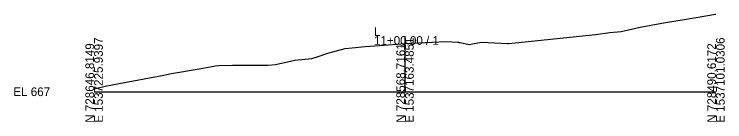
# Model space of a CAD drawing. Extents: x -26 to 1203, y -10 to 9522.
# Drawn here: x -25.7 to 202.8, y 990.3 to 1025 of the extents above; entities that cross this region are included whole.
import ezdxf

# ---------------------------------------------------------------- set-up
doc = ezdxf.new("R2010")
doc.units = 0
for name, color, linetype in [('Default', 7, 'Continuous'), ('Exist Cross Section Cell', 7, 'Continuous'), ('Exist XS Center Line Elevation Label', 7, 'Continuous'), ('Exist XS Ground Line', 7, 'Continuous')]:
    doc.layers.add(name, color=color, linetype=linetype)

msp = doc.modelspace()

# ---------------------------------------------------------------- linework, layer by layer
at = {"layer": 'Exist Cross Section Cell'}
for p, q in [((100, 1000), (100, 1017.92)), ((0, 1000), (100, 1000)), ((100, 1000), (200, 1000))]:
    msp.add_line(p, q, dxfattribs=at)
at = {"layer": 'Exist XS Ground Line'}
msp.add_lwpolyline([(0, 1000.97), (3.54, 1001.77), (8.05, 1002.6), (22.39, 1005.38), (24.94, 1005.89), (34.48, 1007.45), (39.04, 1008.29), (40.12, 1008.45), (44.52, 1008.6), (55.86, 1008.55), (58.33, 1008.8), (64.53, 1010.12), (70.06, 1010.74), (71.74, 1011.29), (75.2, 1012.4), (80.73, 1013.91), (83.04, 1014.18), (87.19, 1014.6), (91.77, 1014.92), (100, 1015.49), (100.13, 1015.5), (108.76, 1015.99), (113.12, 1016.22), (116.94, 1015.96), (117.18, 1015.94), (117.35, 1015.9), (117.66, 1015.85), (120.69, 1015.21), (121.72, 1015.45), (124.55, 1016), (132.97, 1015.51), (133.31, 1015.52), (135.56, 1015.75), (161.21, 1018.45), (165.85, 1019.03), (169.48, 1019.45), (175.59, 1020.8), (182.54, 1022.05), (193.65, 1023.87), (199.84, 1024.96), (200, 1024.98)], dxfattribs=at)

# ---------------------------------------------------------------- texts
at = {"layer": 'Default'}
msp.add_text('-', height=0.0001, dxfattribs=at).set_placement((0, 1000))
msp.add_text('-', height=0.0001, dxfattribs=at).set_placement((0, 1000))
msp.add_text('-', height=0.0001, dxfattribs=at).set_placement((0, 1000))
at = {"layer": 'Exist Cross Section Cell'}
for s, p in [('L', (90, 1017.92)), ('11+00.00 / 1', (90, 1015.12)), ('EL 667', (-26, 998.6))]:
    msp.add_text(s, height=2.8, dxfattribs=at).set_placement(p)
for s, p in [('E 1537225.9397', (2.8, 990)), ('E 1537163.4851', (102.8, 990)), ('E 1537101.0306', (202.8, 990)), ('N 728646.8149', (0, 990)), ('N 728568.7161', (100, 990)), ('N 728490.6172', (200, 990))]:
    msp.add_text(s, height=2.8, rotation=90, dxfattribs=at).set_placement(p)
at = {"layer": 'Exist XS Center Line Elevation Label'}
msp.add_text('682.49', height=0.75, dxfattribs=at).set_placement((98.53, 1014.3))

doc.saveas('drawing.dxf')
